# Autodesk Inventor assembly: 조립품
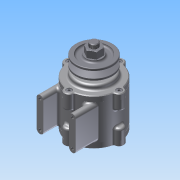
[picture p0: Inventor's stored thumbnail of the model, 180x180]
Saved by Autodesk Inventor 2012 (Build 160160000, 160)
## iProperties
Created: 2007-01
Part Number: 조립품
Document SubType Name: Assembly
Designer: net
Author: net
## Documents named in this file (11)
- C:\Users\net\Desktop\450305V1047\조립품.iam
- C:\Users\net\Desktop\450305V1047\본체.ipt
- C:\Users\net\Desktop\450305V1047\커버2.ipt
- C:\Users\net\Desktop\450305V1047\커버.ipt
- C:\Users\net\Desktop\450305V1047\베어링 6204.ipt
- C:\Users\net\Desktop\450305V1047\축.ipt
- C:\Users\net\Desktop\450305V1047\오일실.ipt
- C:\Users\net\Desktop\450305V1047\키(4 x 4 x 12).ipt
- C:\Users\net\Desktop\450305V1047\V벨트풀리.ipt
- C:\Users\net\Desktop\450305V1047\너트 M12x1.25.ipt
- C:\Users\net\Desktop\450305V1047\M 4 x 12.ipt
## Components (14 placed, 6 different names)
1. KS B 2023 6204 - 20 x 47 x 14:1
2. KS B 2023 6204 - 20 x 47 x 14:2
3. KS B 2804 D D - 20 32 8:1
4. KS B 1311 (I) 4 x 4 x 12:1 — 각도:1, 각도:2
5. 그루브 풀리1:1 — 각도:2
6. KS B 1012 클래스 1 일반 - 미터 M12x1.25:1
7. KS B 1003 - 미터 M 4 x 12:2
8. KS B 1003 - 미터 M 4 x 12:3
9. KS B 1003 - 미터 M 4 x 12:4
10. KS B 1003 - 미터 M 4 x 12:5
11. KS B 1003 - 미터 M 4 x 12:1
12. KS B 1003 - 미터 M 4 x 12:6
13. KS B 1003 - 미터 M 4 x 12:7
14. KS B 1003 - 미터 M 4 x 12:8
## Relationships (2: Angle 2)
- 각도:1 [Angle]: KS B 1311 (I) 4 x 4 x 12:1
- 각도:2 [Angle]: KS B 1311 (I) 4 x 4 x 12:1 ↔ 그루브 풀리1:1
